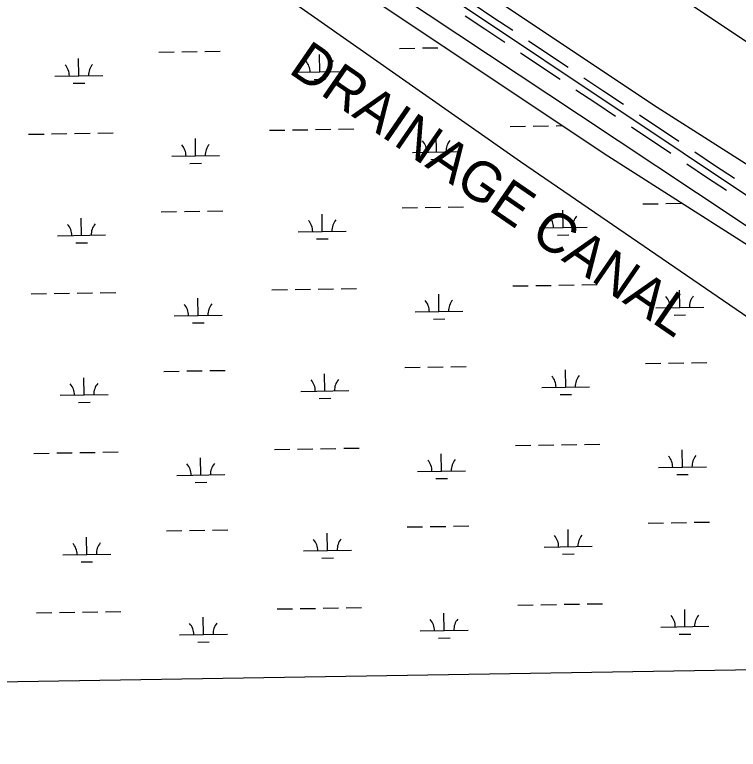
# Model space of a CAD drawing. Extents: x 3855477 to 3893699, y 299188 to 325115.
# Drawn here: x 3868351 to 3869859, y 304617 to 306148 of the extents above; entities that cross this region are included whole.
import ezdxf

# ---------------------------------------------------------------- set-up
doc = ezdxf.new("R2010")
doc.units = 0
for name, color, linetype in [('V-GRID-FRAM', 7, 'Continuous'), ('V-LEVE-TOET', 7, 'Continuous'), ('V-RIVR-IDEN', 7, 'Continuous'), ('V-ROAD-CNTR', 7, 'Continuous'), ('V-TOPO-SHOR', 7, 'Continuous'), ('V-WETL-SWMP', 7, 'Continuous')]:
    doc.layers.add(name, color=color, linetype=linetype)

msp = doc.modelspace()

# ---------------------------------------------------------------- linework, layer by layer
at = {"layer": 'V-GRID-FRAM'}
msp.add_lwpolyline([(3859445.3, 322797), (3891292.6, 323315.8), (3891596.8, 305135.9), (3859733.6, 304616.8), (3859445.3, 322797)], dxfattribs=at)
at = {"layer": 'V-LEVE-TOET'}
for points in [[(3868469.9, 306769.7), (3869690.1, 305955.5), (3870580.6, 305389.5), (3870641.9, 305363.3), (3870661.4, 305356.4), (3870799.2, 305367), (3870835.1, 305363.1), (3870877.1, 305332.9), (3870899.9, 305326), (3871040.7, 305320.2), (3871115.6, 305295.9), (3871161.4, 305295.1), (3871230, 305287.4), (3871282.4, 305286.4), (3871298.9, 305292.7), (3871295.7, 305299.3), (3871306, 305322), (3871332.6, 305347.8)], [(3870184.7, 305500.6), (3869853.1, 305723.3), (3869528.3, 305938.9), (3869148.8, 306191.2)]]:
    msp.add_lwpolyline(points, dxfattribs=at)
at = {"layer": 'V-ROAD-CNTR'}
for points in [[(3866998.4, 307698.3), (3867939.2, 307073.1), (3868877.6, 306439.7), (3870032.7, 305668.1), (3870525.4, 305339.9)], [(3869306.7, 306171.1), (3869348, 306143.5)], [(3869290.1, 306146.1), (3869331.3, 306118.6)], [(3869348, 306143.5), (3869389.2, 306116)], [(3869331.3, 306118.6), (3869372.6, 306091)], [(3869422.2, 306093.9), (3869504.8, 306038.8)], [(3869405.6, 306069), (3869488.1, 306013.9)], [(3869537.8, 306016.8), (3869579, 305989.2)], [(3869521.1, 305991.8), (3869562.3, 305964.3)], [(3869579, 305989.2), (3869620.3, 305961.7)], [(3869562.3, 305964.3), (3869603.6, 305936.7)], [(3869653.3, 305939.6), (3869735.8, 305884.5)], [(3869636.6, 305914.7), (3869719.1, 305859.5)], [(3869768.8, 305862.4), (3869810, 305834.9)], [(3869752.1, 305837.5), (3869793.4, 305809.9)], [(3869810, 305834.9), (3869851.3, 305807.3)], [(3869793.4, 305809.9), (3869834.6, 305782.4)]]:
    msp.add_lwpolyline(points, dxfattribs=at)
at = {"layer": 'V-TOPO-SHOR'}
for points in [[(3870821.2, 305072.6), (3870811.8, 305024.8), (3870660.6, 305055.1), (3870509.4, 305085.3), (3869405.7, 305841.3), (3868846.3, 306234.4)], [(3869689.3, 306217.4), (3869843.2, 306114.4), (3869951.6, 306041.8)]]:
    msp.add_lwpolyline(points, dxfattribs=at)
at = {"layer": 'V-WETL-SWMP'}
for p, q in [((3868996.2, 306249.9), (3869579.6, 305859)), ((3868651.4, 306070), (3868683.4, 306070.6)), ((3868699.4, 306070.8), (3868731.4, 306071.3)), ((3868747.4, 306071.6), (3868779.4, 306072.1)), ((3868987, 306029.1), (3868986.4, 306065.1)), ((3869153.3, 306078.2), (3869185.3, 306078.7)), ((3869201.3, 306079), (3869233.2, 306079.5)), ((3869249.2, 306079.8), (3869250.1, 306079.8)), ((3868485.1, 306020.9), (3868484.5, 306056.9)), ((3868435.1, 306020.1), (3868535.1, 306021.7)), ((3868937, 306028.3), (3869037, 306029.9)), ((3868473.4, 306005.3), (3868497.4, 306005.7)), ((3868975.2, 306013.4), (3868999.2, 306013.8)), ((3869383.9, 305915.4), (3869415.9, 305916)), ((3869431.9, 305916.2), (3869463.9, 305916.7)), ((3869479.9, 305917), (3869492.8, 305917.2)), ((3868380.3, 305899.1), (3868412.3, 305899.6)), ((3868428.2, 305899.9), (3868460.2, 305900.4)), ((3868476.2, 305900.7), (3868508.2, 305901.2)), ((3868524.2, 305901.4), (3868556.2, 305902)), ((3868882.1, 305907.3), (3868914.1, 305907.8)), ((3868930.1, 305908.1), (3868962.1, 305908.6)), ((3868978.1, 305908.8), (3869010.1, 305909.4)), ((3869026.1, 305909.6), (3869058.1, 305910.1)), ((3869230.2, 305862.2), (3869229.6, 305898.2)), ((3868728.4, 305854), (3868727.8, 305890)), ((3868678.4, 305853.2), (3868778.3, 305854.8)), ((3869180.2, 305861.4), (3869280.2, 305863)), ((3869579.6, 305859), (3870103, 305525.7)), ((3868716.6, 305838.4), (3868740.6, 305838.8)), ((3869218.4, 305846.6), (3869242.4, 305847)), ((3869158.7, 305745.6), (3869190.7, 305746.1)), ((3869206.7, 305746.4), (3869238.7, 305746.9)), ((3869254.7, 305747.1), (3869286.7, 305747.7)), ((3869660.5, 305753.8), (3869692.5, 305754.3)), ((3869708.5, 305754.5), (3869740.5, 305755.1)), ((3868656.8, 305737.4), (3868688.8, 305737.9)), ((3868704.8, 305738.2), (3868736.8, 305738.7)), ((3868752.8, 305739), (3868784.8, 305739.5)), ((3868992.4, 305696.4), (3868991.8, 305732.4)), ((3869494.2, 305704.6), (3869493.6, 305740.6)), ((3868490.5, 305688.3), (3868490, 305724.3)), ((3868942.4, 305695.6), (3869042.4, 305697.2)), ((3869444.2, 305703.8), (3869544.2, 305705.4)), ((3868440.6, 305687.4), (3868540.5, 305689.1)), ((3869482.5, 305689), (3869506.5, 305689.4)), ((3868478.8, 305672.6), (3868502.8, 305673)), ((3868980.6, 305680.8), (3869004.6, 305681.2)), ((3868887.5, 305574.6), (3868919.5, 305575.2)), ((3868935.5, 305575.4), (3868967.5, 305575.9)), ((3868983.5, 305576.2), (3869015.5, 305576.7)), ((3869031.5, 305577), (3869063.5, 305577.5)), ((3869389.4, 305582.8), (3869421.4, 305583.3)), ((3869437.4, 305583.6), (3869469.3, 305584.1)), ((3869485.3, 305584.4), (3869517.3, 305584.9)), ((3869533.3, 305585.2), (3869565.3, 305585.7)), ((3868385.7, 305566.5), (3868417.7, 305567)), ((3868433.7, 305567.2), (3868465.7, 305567.8)), ((3868481.7, 305568), (3868513.7, 305568.5)), ((3868529.7, 305568.8), (3868561.7, 305569.3)), ((3869235.6, 305529.6), (3869235, 305565.6)), ((3869737.5, 305537.7), (3869736.9, 305573.7)), ((3868733.8, 305521.4), (3868733.2, 305557.4)), ((3869185.6, 305528.7), (3869285.6, 305530.4)), ((3869687.5, 305536.9), (3869787.4, 305538.6)), ((3868683.8, 305520.6), (3868783.8, 305522.2)), ((3869223.9, 305513.9), (3869247.9, 305514.3)), ((3869725.7, 305522.1), (3869749.7, 305522.5)), ((3868722, 305505.8), (3868746, 305506.2)), ((3869665.9, 305421.1), (3869697.9, 305421.6)), ((3869713.9, 305421.9), (3869745.9, 305422.4)), ((3869761.9, 305422.7), (3869793.9, 305423.2)), ((3868758.2, 305406.3), (3868790.2, 305406.9)), ((3869164.1, 305412.9), (3869196.1, 305413.5)), ((3869212.1, 305413.7), (3869244.1, 305414.3)), ((3869260.1, 305414.5), (3869292.1, 305415)), ((3869499.7, 305372), (3869499.1, 305408)), ((3868496, 305355.6), (3868495.4, 305391.6)), ((3868662.3, 305404.8), (3868694.2, 305405.3)), ((3868710.2, 305405.6), (3868742.2, 305406.1)), ((3868997.8, 305363.8), (3868997.2, 305399.8)), ((3868947.8, 305363), (3869047.8, 305364.6)), ((3869449.7, 305371.2), (3869549.6, 305372.8)), ((3868446, 305354.8), (3868546, 305356.4)), ((3868986.1, 305348.2), (3869010.1, 305348.6)), ((3869487.9, 305356.4), (3869511.9, 305356.7)), ((3868484.2, 305340), (3868508.2, 305340.4)), ((3868892.9, 305242), (3868924.9, 305242.5)), ((3868940.9, 305242.8), (3868972.9, 305243.3)), ((3868988.9, 305243.6), (3869020.9, 305244.1)), ((3869036.9, 305244.4), (3869068.9, 305244.9)), ((3869394.8, 305250.2), (3869426.8, 305250.7)), ((3869442.8, 305251), (3869474.8, 305251.5)), ((3869490.8, 305251.7), (3869522.8, 305252.3)), ((3869538.8, 305252.5), (3869570.8, 305253.1)), ((3869742.9, 305205.1), (3869742.3, 305241.1)), ((3868391.1, 305233.8), (3868423.1, 305234.4)), ((3868439.1, 305234.6), (3868471.1, 305235.1)), ((3868487.1, 305235.4), (3868519.1, 305235.9)), ((3868535.1, 305236.2), (3868567.1, 305236.7)), ((3868739.2, 305188.8), (3868738.6, 305224.8)), ((3869241, 305196.9), (3869240.4, 305232.9)), ((3869191, 305196.1), (3869291, 305197.7)), ((3869692.9, 305204.3), (3869792.9, 305205.9)), ((3868689.2, 305187.9), (3868789.2, 305189.6)), ((3869229.3, 305181.3), (3869253.3, 305181.7)), ((3869731.1, 305189.5), (3869755.1, 305189.9)), ((3868727.4, 305173.1), (3868751.4, 305173.5)), ((3869671.4, 305088.5), (3869703.4, 305089)), ((3869719.3, 305089.3), (3869751.3, 305089.8)), ((3869767.3, 305090.1), (3869799.3, 305090.6)), ((3868667.7, 305072.1), (3868699.7, 305072.7)), ((3868715.7, 305072.9), (3868747.7, 305073.4)), ((3868763.7, 305073.7), (3868795.7, 305074.2)), ((3869169.5, 305080.3), (3869201.5, 305080.8)), ((3869217.5, 305081.1), (3869249.5, 305081.6)), ((3869265.5, 305081.9), (3869297.5, 305082.4)), ((3869505.1, 305039.3), (3869504.5, 305075.3)), ((3868501.4, 305023), (3868500.8, 305059)), ((3869003.2, 305031.2), (3869002.6, 305067.2)), ((3869455.1, 305038.5), (3869555.1, 305040.2)), ((3868451.4, 305022.2), (3868551.4, 305023.8)), ((3868953.2, 305030.4), (3869053.2, 305032)), ((3869493.3, 305023.7), (3869517.3, 305024.1)), ((3868991.5, 305015.5), (3869015.5, 305015.9)), ((3868489.6, 305007.4), (3868513.6, 305007.8)), ((3869400.2, 304917.6), (3869432.2, 304918.1)), ((3869448.2, 304918.3), (3869480.2, 304918.9)), ((3869496.2, 304919.1), (3869528.2, 304919.6)), ((3869544.2, 304919.9), (3869576.2, 304920.4)), ((3868396.5, 304901.2), (3868428.5, 304901.7)), ((3868444.5, 304902), (3868476.5, 304902.5)), ((3868492.5, 304902.8), (3868524.5, 304903.3)), ((3868540.5, 304903.5), (3868572.5, 304904.1)), ((3868898.4, 304909.4), (3868930.4, 304909.9)), ((3868946.3, 304910.2), (3868978.3, 304910.7)), ((3868994.3, 304910.9), (3869026.3, 304911.5)), ((3869042.3, 304911.7), (3869074.3, 304912.2)), ((3869748.3, 304872.5), (3869747.7, 304908.5)), ((3868744.6, 304856.1), (3868744, 304892.1)), ((3869246.5, 304864.3), (3869245.9, 304900.3)), ((3869698.3, 304871.7), (3869798.3, 304873.3)), ((3868694.6, 304855.3), (3868794.6, 304856.9)), ((3869196.5, 304863.5), (3869296.4, 304865.1)), ((3869736.5, 304856.9), (3869760.5, 304857.2)), ((3868732.9, 304840.5), (3868756.9, 304840.9)), ((3869234.7, 304848.7), (3869258.7, 304849.1)), ((3870951.5, 304799.6), (3866336.8, 304724.4))]:
    msp.add_line(p, q, dxfattribs=at)
for centre, start, end in [((3868931.7, 306028.6), 0.1615, 41.7052), ((3869042.2, 306030.4), 140.1615, 181.7052), ((3868429.9, 306020.5), 0.1615, 41.7052), ((3868540.4, 306022.3), 140.1615, 181.7052), ((3869175, 305861.8), 0.1615, 41.7052), ((3869285.4, 305863.6), 140.1615, 181.7052), ((3868673.1, 305853.6), 0.1615, 41.7052), ((3868783.6, 305855.4), 140.1615, 181.7052), ((3869549.5, 305706), 140.1615, 181.7052), ((3868937.1, 305696), 0.1615, 41.7052), ((3869047.6, 305697.8), 140.1615, 181.7052), ((3869439, 305704.2), 0.1615, 41.7052), ((3868435.3, 305687.8), 0.1615, 41.7052), ((3868545.8, 305689.6), 140.1615, 181.7052), ((3869682.2, 305537.3), 0.1615, 41.7052), ((3869792.7, 305539.1), 140.1615, 181.7052), ((3868678.5, 305521), 0.1615, 41.7052), ((3868789, 305522.8), 140.1615, 181.7052), ((3869180.4, 305529.1), 0.1615, 41.7052), ((3869290.8, 305530.9), 140.1615, 181.7052), ((3869444.4, 305371.6), 0.1615, 41.7052), ((3869554.9, 305373.4), 140.1615, 181.7052), ((3868440.7, 305355.2), 0.1615, 41.7052), ((3868551.2, 305357), 140.1615, 181.7052), ((3868942.6, 305363.4), 0.1615, 41.7052), ((3869053, 305365.2), 140.1615, 181.7052), ((3869687.6, 305204.7), 0.1615, 41.7052), ((3869798.1, 305206.5), 140.1615, 181.7052), ((3868683.9, 305188.3), 0.1615, 41.7052), ((3868794.4, 305190.1), 140.1615, 181.7052), ((3869185.8, 305196.5), 0.1615, 41.7052), ((3869296.3, 305198.3), 140.1615, 181.7052), ((3868948, 305030.7), 0.1615, 41.7052), ((3869058.5, 305032.5), 140.1615, 181.7052), ((3869449.8, 305038.9), 0.1615, 41.7052), ((3869560.3, 305040.7), 140.1615, 181.7052), ((3868446.1, 305022.6), 0.1615, 41.7052), ((3868556.6, 305024.4), 140.1615, 181.7052), ((3869191.2, 304863.9), 0.1615, 41.7052), ((3869301.7, 304865.7), 140.1615, 181.7052), ((3869693, 304872.1), 0.1615, 41.7052), ((3869803.5, 304873.9), 140.1615, 181.7052), ((3868689.4, 304855.7), 0.1615, 41.7052), ((3868799.8, 304857.5), 140.1615, 181.7052)]:
    msp.add_arc(centre, 35.2, start, end, dxfattribs=at)

# ---------------------------------------------------------------- texts
at = {"layer": 'V-RIVR-IDEN'}
msp.add_text('DRAINAGE CANAL', height=83, rotation=325.4854, dxfattribs=at).set_placement((3868919.6, 306028.9))

doc.saveas('drawing.dxf')
